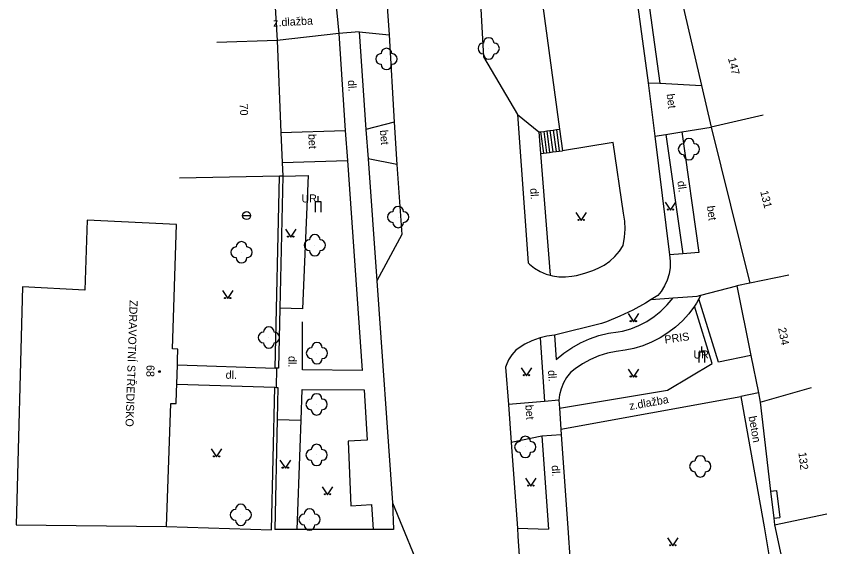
# Model space of a CAD drawing. Extents: x -544674 to -541478, y -1199076 to -1195527.
# Drawn here: x -542681.8 to -542605.9, y -1198327.4 to -1198277.7 of the extents above; entities that cross this region are included whole.
import ezdxf

# ---------------------------------------------------------------- set-up
doc = ezdxf.new("R2010")
doc.units = 0
for name, color, linetype in [('BUDOVY_MĚŘ', 7, 'Continuous'), ('BUDOVY_NEMĚŘ', 7, 'Continuous'), ('POMOC_POPIS', 7, 'Continuous'), ('ROZHRANÍ_PLOCH', 7, 'Continuous'), ('ZELEŇ', 7, 'Continuous'), ('ZN_BUDOV', 7, 'Continuous'), ('ZN_DOPLŇKOVÉ', 7, 'Continuous'), ('ZN_KULTUR', 7, 'Continuous'), ('Č_POPIS_ORIENT', 7, 'Continuous')]:
    doc.layers.add(name, color=color, linetype=linetype)

msp = doc.modelspace()

# ---------------------------------------------------------------- linework, layer by layer
at = {"layer": 'BUDOVY_MĚŘ'}
for points in [[(-542657.56, -1198276.32), (-542657.37, -1198279.94)], [(-542619.43, -1198276.39), (-542617.61, -1198284.16)], [(-542657.37, -1198279.94), (-542663, -1198280.14)], [(-542657.37, -1198279.94), (-542657, -1198288.56)], [(-542617.61, -1198284.16), (-542616.69, -1198288.07)], [(-542611.82, -1198286.93), (-542616.69, -1198288.07)], [(-542616.69, -1198288.07), (-542613.08, -1198302.67)], [(-542657, -1198288.56), (-542656.88, -1198291.36)], [(-542656.88, -1198291.36), (-542656.83, -1198292.64)], [(-542657.13, -1198292.65), (-542666.5, -1198292.84)], [(-542656.83, -1198292.64), (-542657.13, -1198292.65)], [(-542667.16, -1198308.84), (-542666.77, -1198297.18)], [(-542609.41, -1198301.93), (-542613.08, -1198302.67)], [(-542613.08, -1198302.67), (-542614.31, -1198302.92)], [(-542614.31, -1198302.92), (-542612.99, -1198309.46)], [(-542666.65, -1198308.86), (-542667.16, -1198308.84)], [(-542666.68, -1198309.89), (-542666.65, -1198308.86)], [(-542612.99, -1198309.46), (-542612.28, -1198312.96)], [(-542666.76, -1198312.12), (-542666.7, -1198310.32)], [(-542666.7, -1198310.32), (-542666.68, -1198309.89)], [(-542666.78, -1198312.85), (-542666.76, -1198312.12)], [(-542612.11, -1198313.81), (-542607.3, -1198312.44)], [(-542666.82, -1198313.96), (-542666.78, -1198312.85)], [(-542612.28, -1198312.96), (-542612.11, -1198313.81)], [(-542667.72, -1198325.46), (-542667.33, -1198313.94)], [(-542667.33, -1198313.94), (-542666.82, -1198313.96)], [(-542612.11, -1198313.81), (-542611.13, -1198322.15)], [(-542611.13, -1198322.15), (-542610.83, -1198324.68)], [(-542610.83, -1198324.68), (-542610.76, -1198325.3)], [(-542610.76, -1198325.3), (-542605.87, -1198324.27)], [(-542610.76, -1198325.3), (-542609.26, -1198332.28)]]:
    msp.add_lwpolyline(points, dxfattribs=at)
at = {"layer": 'BUDOVY_NEMĚŘ'}
for points in [[(-542675.14, -1198296.77), (-542675.36, -1198303.34)], [(-542666.77, -1198297.18), (-542675.14, -1198296.77)], [(-542681.21, -1198303.01), (-542681.8, -1198325.3)], [(-542675.36, -1198303.34), (-542681.21, -1198303.01)], [(-542681.8, -1198325.3), (-542667.72, -1198325.46)]]:
    msp.add_lwpolyline(points, dxfattribs=at)
at = {"layer": 'ROZHRANÍ_PLOCH'}
for points in [[(-542634.09, -1198240.3), (-542634.58, -1198240.65), (-542635.02, -1198241.06), (-542635.35, -1198241.45), (-542635.99, -1198242.82), (-542636.56, -1198244.22), (-542637.05, -1198245.65), (-542637.47, -1198247.1), (-542637.81, -1198248.57), (-542638.07, -1198250.06), (-542638.25, -1198251.56), (-542638.35, -1198253.07), (-542638.37, -1198254.58), (-542638.36, -1198255.17), (-542638.8, -1198267.4), (-542638.02, -1198281.47), (-542634.85, -1198286.86)], [(-542635.21, -1198256.43), (-542630.9, -1198288.25)], [(-542625.49, -1198262.77), (-542624.44, -1198262.62), (-542621.52, -1198283.95)], [(-542625.49, -1198262.77), (-542622.6, -1198283.89)], [(-542647.15, -1198275.4), (-542646.87, -1198279.41)], [(-542651.88, -1198276.02), (-542651.59, -1198279.27)], [(-542651.59, -1198279.27), (-542657.37, -1198279.94)], [(-542649.67, -1198279.14), (-542651.59, -1198279.27)], [(-542651.59, -1198279.27), (-542650.98, -1198288.37)], [(-542649.67, -1198279.14), (-542649.04, -1198288.29)], [(-542649.67, -1198279.14), (-542646.87, -1198279.41)], [(-542646.87, -1198279.41), (-542646.38, -1198287.58)], [(-542622.6, -1198283.89), (-542621.97, -1198288.89)], [(-542622.6, -1198283.89), (-542621.52, -1198283.95)], [(-542621.52, -1198283.95), (-542617.61, -1198284.16)], [(-542634.85, -1198286.86), (-542632.84, -1198288.51)], [(-542634.85, -1198286.86), (-542633.85, -1198300.76), (-542633.72, -1198300.89), (-542633.24, -1198301.27), (-542632.72, -1198301.58), (-542632.16, -1198301.82), (-542631.78, -1198301.93)], [(-542646.38, -1198287.58), (-542649.04, -1198288.29)], [(-542646.38, -1198287.58), (-542646.14, -1198291.57)], [(-542657, -1198288.56), (-542650.98, -1198288.37)], [(-542650.98, -1198288.37), (-542650.78, -1198291.17)], [(-542649.04, -1198288.29), (-542648.84, -1198291.03)], [(-542632.84, -1198288.51), (-542632.69, -1198288.49)], [(-542632.84, -1198288.51), (-542632.68, -1198290.53)], [(-542632.69, -1198288.49), (-542632.39, -1198288.45)], [(-542632.69, -1198288.49), (-542632.42, -1198290.5)], [(-542632.39, -1198288.45), (-542632.09, -1198288.41)], [(-542632.39, -1198288.45), (-542632.13, -1198290.46)], [(-542632.09, -1198288.41), (-542631.8, -1198288.37)], [(-542632.09, -1198288.41), (-542631.83, -1198290.42)], [(-542631.8, -1198288.37), (-542631.5, -1198288.33)], [(-542631.8, -1198288.37), (-542631.53, -1198290.38)], [(-542631.5, -1198288.33), (-542631.2, -1198288.29)], [(-542631.5, -1198288.33), (-542631.23, -1198290.34)], [(-542631.2, -1198288.29), (-542630.9, -1198288.25)], [(-542631.2, -1198288.29), (-542630.94, -1198290.3)], [(-542630.9, -1198288.25), (-542630.64, -1198290.26)], [(-542620.94, -1198288.73), (-542619.46, -1198288.5)], [(-542619.46, -1198288.5), (-542616.69, -1198288.07)], [(-542619.46, -1198288.5), (-542617.87, -1198299.8), (-542619.37, -1198299.92)], [(-542621.97, -1198288.89), (-542620.94, -1198288.73)], [(-542621.97, -1198288.89), (-542620.59, -1198300.01)], [(-542620.94, -1198288.73), (-542619.37, -1198299.92)], [(-542631.78, -1198301.93), (-542631.57, -1198301.99), (-542630.97, -1198302.08), (-542630.36, -1198302.09), (-542629.75, -1198302.02), (-542629.31, -1198301.95), (-542628.54, -1198301.75), (-542627.78, -1198301.48), (-542627.29, -1198301.28), (-542626.72, -1198300.98), (-542626.2, -1198300.6), (-542625.72, -1198300.16), (-542625.3, -1198299.67), (-542624.95, -1198299.13), (-542624.82, -1198298.37), (-542624.77, -1198297.61), (-542624.8, -1198296.85), (-542624.91, -1198296.1), (-542625.89, -1198289.49), (-542630.64, -1198290.26)], [(-542632.68, -1198290.53), (-542632.42, -1198290.5)], [(-542632.68, -1198290.53), (-542631.78, -1198301.93)], [(-542632.42, -1198290.5), (-542632.13, -1198290.46)], [(-542632.13, -1198290.46), (-542631.83, -1198290.42)], [(-542631.83, -1198290.42), (-542631.53, -1198290.38)], [(-542631.53, -1198290.38), (-542631.23, -1198290.34)], [(-542631.23, -1198290.34), (-542630.94, -1198290.3)], [(-542630.94, -1198290.3), (-542630.64, -1198290.26)], [(-542656.88, -1198291.36), (-542650.78, -1198291.17)], [(-542650.78, -1198291.17), (-542649.38, -1198310.85), (-542654.98, -1198310.8), (-542654.98, -1198306.28)], [(-542648.84, -1198291.03), (-542648.03, -1198302.44)], [(-542646.14, -1198291.57), (-542648.84, -1198291.03)], [(-542646.14, -1198291.57), (-542645.67, -1198298.1), (-542648.03, -1198302.44)], [(-542656.83, -1198292.64), (-542654.45, -1198292.59), (-542654.98, -1198305.08), (-542657.11, -1198305.03)], [(-542619.37, -1198299.92), (-542620.59, -1198300.01)], [(-542620.59, -1198300.01), (-542620.53, -1198300.61), (-542620.55, -1198301.21), (-542620.65, -1198301.81), (-542620.82, -1198302.38), (-542621.07, -1198302.93), (-542621.39, -1198303.44), (-542621.7, -1198303.82), (-542622.32, -1198304.21)], [(-542648.03, -1198302.44), (-542646.54, -1198323.24)], [(-542617.67, -1198303.79), (-542614.31, -1198302.92)], [(-542631.37, -1198307.53), (-542631.22, -1198309.82), (-542630.5, -1198309.24), (-542629.74, -1198308.72), (-542628.93, -1198308.27), (-542628.09, -1198307.9), (-542627.21, -1198307.59), (-542626.32, -1198307.37), (-542625.41, -1198307.22), (-542625.02, -1198307.18), (-542624.23, -1198306.95), (-542623.47, -1198306.64), (-542622.74, -1198306.26), (-542622.05, -1198305.81), (-542621.41, -1198305.29), (-542620.82, -1198304.71), (-542620.26, -1198304.05)], [(-542622.32, -1198304.21), (-542622.85, -1198304.54), (-542624.03, -1198305.19), (-542625.25, -1198305.78), (-542626.51, -1198306.28), (-542626.97, -1198306.45), (-542631.37, -1198307.53)], [(-542622.32, -1198304.21), (-542620.26, -1198304.05)], [(-542620.26, -1198304.05), (-542618.01, -1198303.88), (-542617.67, -1198303.79)], [(-542617.85, -1198304.13), (-542618.09, -1198304.55), (-542618.26, -1198304.83)], [(-542617.67, -1198303.79), (-542617.85, -1198304.13)], [(-542612.99, -1198309.46), (-542616.01, -1198310.07), (-542617.85, -1198304.13)], [(-542618.26, -1198304.83), (-542618.79, -1198305.54), (-542619.39, -1198306.19), (-542620.04, -1198306.79), (-542620.75, -1198307.33), (-542621.49, -1198307.8), (-542622.28, -1198308.21), (-542623.11, -1198308.54), (-542623.95, -1198308.79), (-542624.75, -1198308.96), (-542625.59, -1198309.06), (-542626.42, -1198309.24), (-542627.22, -1198309.49), (-542628, -1198309.82), (-542628.74, -1198310.22), (-542629.44, -1198310.69), (-542629.88, -1198311.04), (-542630.24, -1198311.51), (-542630.54, -1198312.02), (-542630.76, -1198312.57), (-542630.91, -1198313.15), (-542630.97, -1198313.64)], [(-542630.92, -1198314.38), (-542620.8, -1198312.7), (-542616.6, -1198310.19), (-542618.26, -1198304.83)], [(-542632.71, -1198307.79), (-542632.82, -1198307.81), (-542633.51, -1198308.07), (-542634.17, -1198308.4), (-542634.79, -1198308.8), (-542634.99, -1198308.95), (-542635.36, -1198309.38), (-542635.67, -1198309.87), (-542635.91, -1198310.39), (-542635.96, -1198310.53), (-542635.7, -1198314.03)], [(-542631.37, -1198307.53), (-542632.1, -1198307.63), (-542632.71, -1198307.79)], [(-542632.71, -1198307.79), (-542632.32, -1198313.75)], [(-542666.7, -1198310.32), (-542657.54, -1198310.63)], [(-542666.76, -1198312.12), (-542657.58, -1198312.43)], [(-542655.1, -1198315.5), (-542655, -1198312.63), (-542649.22, -1198312.68), (-542648.92, -1198317.38), (-542650.69, -1198317.49), (-542650.44, -1198323.54), (-542648.52, -1198323.42), (-542648.37, -1198325.75)], [(-542630.78, -1198316.34), (-542613.91, -1198313.29)], [(-542613.91, -1198313.29), (-542611.74, -1198325.51), (-542610.23, -1198334.5), (-542629.28, -1198337.6)], [(-542612.28, -1198312.96), (-542613.91, -1198313.29)], [(-542632.32, -1198313.75), (-542635.7, -1198314.03)], [(-542635.7, -1198314.03), (-542635.44, -1198317.59)], [(-542630.97, -1198313.64), (-542632.32, -1198313.75)], [(-542630.97, -1198313.64), (-542630.92, -1198314.38)], [(-542630.92, -1198314.38), (-542630.78, -1198316.34)], [(-542657.35, -1198315.45), (-542655.1, -1198315.5)], [(-542655.47, -1198325.76), (-542655.1, -1198315.5)], [(-542630.78, -1198316.34), (-542630.74, -1198316.87)], [(-542632.56, -1198317), (-542635.44, -1198317.59)], [(-542630.74, -1198316.87), (-542632.56, -1198317)], [(-542632.56, -1198317), (-542631.94, -1198325.73)], [(-542630.74, -1198316.87), (-542630.13, -1198325.6)], [(-542635.44, -1198317.59), (-542634.85, -1198325.64)], [(-542611.13, -1198322.15), (-542610.57, -1198322.09)], [(-542610.57, -1198322.09), (-542610.28, -1198324.62)], [(-542646.54, -1198323.24), (-542646.46, -1198325.75), (-542648.37, -1198325.75)], [(-542646.54, -1198323.24), (-542643.52, -1198330.61)], [(-542610.83, -1198324.68), (-542610.28, -1198324.62)], [(-542667.72, -1198325.46), (-542657.88, -1198325.78)], [(-542634.85, -1198325.64), (-542634.8, -1198326.37), (-542634.53, -1198330.54)], [(-542634.85, -1198325.64), (-542631.94, -1198325.73)], [(-542630.13, -1198325.6), (-542629.9, -1198328.85)], [(-542655.47, -1198325.76), (-542657.58, -1198325.76)], [(-542648.37, -1198325.75), (-542655.47, -1198325.76)]]:
    msp.add_lwpolyline(points, dxfattribs=at)
at = {"layer": 'ZELEŇ'}
for centre in [(-542637.54, -1198280.68), (-542647.12, -1198281.67), (-542618.78, -1198290.12), (-542646.02, -1198296.48), (-542653.83, -1198299.12), (-542660.69, -1198299.78), (-542658.14, -1198307.76), (-542653.63, -1198309.23), (-542653.66, -1198314.03), (-542634.11, -1198318.02), (-542653.66, -1198318.77), (-542617.72, -1198319.84), (-542660.76, -1198324.38), (-542654.32, -1198324.81)]:
    msp.add_circle(centre, 0.0005, dxfattribs=at)
for centre, start, end in [((-542638.04, -1198280.68), 89.99999, 269.99999), ((-542637.54, -1198280.18), 0, 179.99999), ((-542637.04, -1198280.68), 270, 89.99999), ((-542647.12, -1198281.17), 0, 179.99999), ((-542647.62, -1198281.67), 89.99999, 269.99999), ((-542646.62, -1198281.67), 270, 89.99999), ((-542637.54, -1198281.18), 179.99999, 359.99999), ((-542647.12, -1198282.17), 179.99999, 359.99999), ((-542618.78, -1198289.62), 0, 179.99999), ((-542619.28, -1198290.12), 89.99999, 269.99999), ((-542618.28, -1198290.12), 270, 89.99999), ((-542618.78, -1198290.62), 179.99999, 359.99999), ((-542646.52, -1198296.48), 89.99999, 269.99999), ((-542646.02, -1198295.98), 0, 179.99999), ((-542645.52, -1198296.48), 270, 89.99999), ((-542646.02, -1198296.98), 179.99999, 359.99999), ((-542653.83, -1198298.62), 0, 179.99999), ((-542660.69, -1198299.28), 0, 179.99999), ((-542654.33, -1198299.12), 89.99999, 269.99999), ((-542653.33, -1198299.12), 270, 89.99999), ((-542661.19, -1198299.78), 89.99999, 269.99999), ((-542660.19, -1198299.78), 270, 89.99999), ((-542653.83, -1198299.62), 179.99999, 359.99999), ((-542660.69, -1198300.28), 179.99999, 359.99999), ((-542658.64, -1198307.76), 89.99999, 269.99999), ((-542658.14, -1198307.26), 0, 179.99999), ((-542657.64, -1198307.76), 270, 89.99999), ((-542658.14, -1198308.26), 179.99999, 359.99999), ((-542653.63, -1198308.73), 0, 179.99999), ((-542654.13, -1198309.23), 89.99999, 269.99999), ((-542653.13, -1198309.23), 270, 89.99999), ((-542653.63, -1198309.73), 179.99999, 359.99999), ((-542654.16, -1198314.03), 89.99999, 269.99999), ((-542653.66, -1198313.53), 0, 179.99999), ((-542653.16, -1198314.03), 270, 89.99999), ((-542653.66, -1198314.53), 179.99999, 359.99999), ((-542634.11, -1198317.52), 0, 179.99999), ((-542653.66, -1198318.27), 0, 179.99999), ((-542634.61, -1198318.02), 89.99999, 269.99999), ((-542633.61, -1198318.02), 270, 89.99999), ((-542654.16, -1198318.77), 89.99999, 269.99999), ((-542653.16, -1198318.77), 270, 89.99999), ((-542634.11, -1198318.52), 179.99999, 359.99999), ((-542617.72, -1198319.34), 0, 179.99999), ((-542653.66, -1198319.27), 179.99999, 359.99999), ((-542618.22, -1198319.84), 89.99999, 269.99999), ((-542617.22, -1198319.84), 270, 89.99999), ((-542617.72, -1198320.34), 179.99999, 359.99999), ((-542660.76, -1198323.88), 0, 179.99999), ((-542661.26, -1198324.38), 89.99999, 269.99999), ((-542660.26, -1198324.38), 270, 89.99999), ((-542654.32, -1198324.31), 0, 179.99999), ((-542660.76, -1198324.88), 179.99999, 359.99999), ((-542654.82, -1198324.81), 89.99999, 269.99999), ((-542653.82, -1198324.81), 270, 89.99999), ((-542654.32, -1198325.31), 179.99999, 359.99999)]:
    msp.add_arc(centre, 0.5, start, end, dxfattribs=at)
at = {"layer": 'ZN_BUDOV'}
msp.add_circle((-542668.39, -1198310.96), 0.0875, dxfattribs=at)
at = {"layer": 'ZN_DOPLŇKOVÉ'}
for p, q in [((-542653.52, -1198295.01), (-542653.52, -1198294.51)), ((-542660.595, -1198296.34), (-542659.845, -1198296.34)), ((-542617.56, -1198309.12), (-542617.56, -1198308.62))]:
    msp.add_line(p, q, dxfattribs=at)
for points in [[(-542657.54, -1198310.63), (-542657.13, -1198292.65)], [(-542656.83, -1198292.64), (-542657.11, -1198305.03)], [(-542653.77, -1198296.01), (-542653.77, -1198295.01), (-542653.27, -1198295.01), (-542653.27, -1198296.01)], [(-542657.11, -1198305.03), (-542657.24, -1198310.63), (-542657.39, -1198310.63)], [(-542617.81, -1198310.12), (-542617.81, -1198309.12), (-542617.31, -1198309.12), (-542617.31, -1198310.12)], [(-542657.39, -1198310.63), (-542657.54, -1198310.63)], [(-542657.42, -1198312.44), (-542657.39, -1198310.63)], [(-542657.88, -1198325.78), (-542657.58, -1198312.43)], [(-542657.58, -1198312.43), (-542657.42, -1198312.44)], [(-542657.42, -1198312.44), (-542657.28, -1198312.44), (-542657.35, -1198315.45)], [(-542657.35, -1198315.45), (-542657.58, -1198325.76)]]:
    msp.add_lwpolyline(points, dxfattribs=at)
msp.add_circle((-542660.22, -1198296.34), 0.375, dxfattribs=at)
at = {"layer": 'ZN_KULTUR'}
for points in [[(-542621.01, -1198295.08), (-542620.51, -1198295.83), (-542620.01, -1198295.08)], [(-542629.37, -1198296.05), (-542628.87, -1198296.8), (-542628.37, -1198296.05)], [(-542656.59, -1198297.61), (-542656.09, -1198298.36), (-542655.59, -1198297.61)], [(-542662.49, -1198303.37), (-542661.99, -1198304.12), (-542661.49, -1198303.37)], [(-542624.49, -1198305.53), (-542623.99, -1198306.28), (-542623.49, -1198305.53)], [(-542634.49, -1198310.59), (-542633.99, -1198311.34), (-542633.49, -1198310.59)], [(-542624.49, -1198310.72), (-542623.99, -1198311.47), (-542623.49, -1198310.72)], [(-542663.53, -1198318.2), (-542663.03, -1198318.95), (-542662.53, -1198318.2)], [(-542657.09, -1198319.26), (-542656.59, -1198320.01), (-542656.09, -1198319.26)], [(-542634.1, -1198320.94), (-542633.6, -1198321.69), (-542633.1, -1198320.94)], [(-542653.13, -1198321.75), (-542652.63, -1198322.5), (-542652.13, -1198321.75)], [(-542620.8, -1198326.53), (-542620.3, -1198327.28), (-542619.8, -1198326.53)]]:
    msp.add_lwpolyline(points, dxfattribs=at)
for centre in [(-542620.76, -1198295.78), (-542620.26, -1198295.78), (-542629.12, -1198296.75), (-542628.62, -1198296.75), (-542656.34, -1198298.31), (-542655.84, -1198298.31), (-542662.24, -1198304.07), (-542661.74, -1198304.07), (-542624.24, -1198306.23), (-542623.74, -1198306.23), (-542634.24, -1198311.29), (-542633.74, -1198311.29), (-542624.24, -1198311.42), (-542623.74, -1198311.42), (-542663.28, -1198318.9), (-542662.78, -1198318.9), (-542656.84, -1198319.96), (-542656.34, -1198319.96), (-542633.85, -1198321.64), (-542633.35, -1198321.64), (-542652.88, -1198322.45), (-542652.38, -1198322.45), (-542620.55, -1198327.23), (-542620.05, -1198327.23)]:
    msp.add_circle(centre, 0.05, dxfattribs=at)

# ---------------------------------------------------------------- texts
at = {"layer": 'POMOC_POPIS'}
for s, rotation, p in [('z.dlažba', 3.06, (-542657.72, -1198278.64)), ('dl.', 274.09, (-542650.74, -1198283.67)), ('bet', 277.18002, (-542620.88, -1198284.97)), ('bet', 275.10001, (-542647.74, -1198288.35)), ('bet', 272.42997, (-542654.44, -1198288.71)), ('dl.', 274.11, (-542633.66, -1198293.8)), ('dl.', 277.99998, (-542619.87, -1198293.14)), ('bet', 277.18002, (-542617.1, -1198295.46)), ('ZDRAVOTNÍ STŘEDISKO', 268.08002, (-542671.17, -1198304.25)), ('PRIS', 8.05, (-542621.02, -1198308.34)), ('dl.', 268.68999, (-542656.29, -1198309.49)), ('dl.', 358.08, (-542662.19, -1198311.62)), ('dl.', 273.73998, (-542631.99, -1198310.84)), ('z.dlažba', 10.24002, (-542624.31, -1198314.56)), ('bet', 274.18998, (-542634.11, -1198314.09)), ('beton', 280.07999, (-542613.2, -1198315.18)), ('dl.', 273.73998, (-542631.65, -1198319.75))]:
    msp.add_text(s, height=0.75, rotation=rotation, dxfattribs=at).set_placement(p)
for p in [(-542655.08, -1198295.11), (-542618.37, -1198309.73)]:
    msp.add_text('UR', height=0.75, dxfattribs=at).set_placement(p)
at = {"layer": 'Č_POPIS_ORIENT'}
for s, rotation, p in [('147', 283.21, (-542615.13, -1198281.6)), ('70', 272.42997, (-542660.87, -1198285.87)), ('131', 283.86999, (-542612.11, -1198294.09)), ('234', 281.42002, (-542610.44, -1198306.9)), ('68', 268.59998, (-542669.59, -1198310.33)), ('132', 276.7, (-542608.53, -1198318.54))]:
    msp.add_text(s, height=0.75, rotation=rotation, dxfattribs=at).set_placement(p)

doc.saveas('drawing.dxf')
